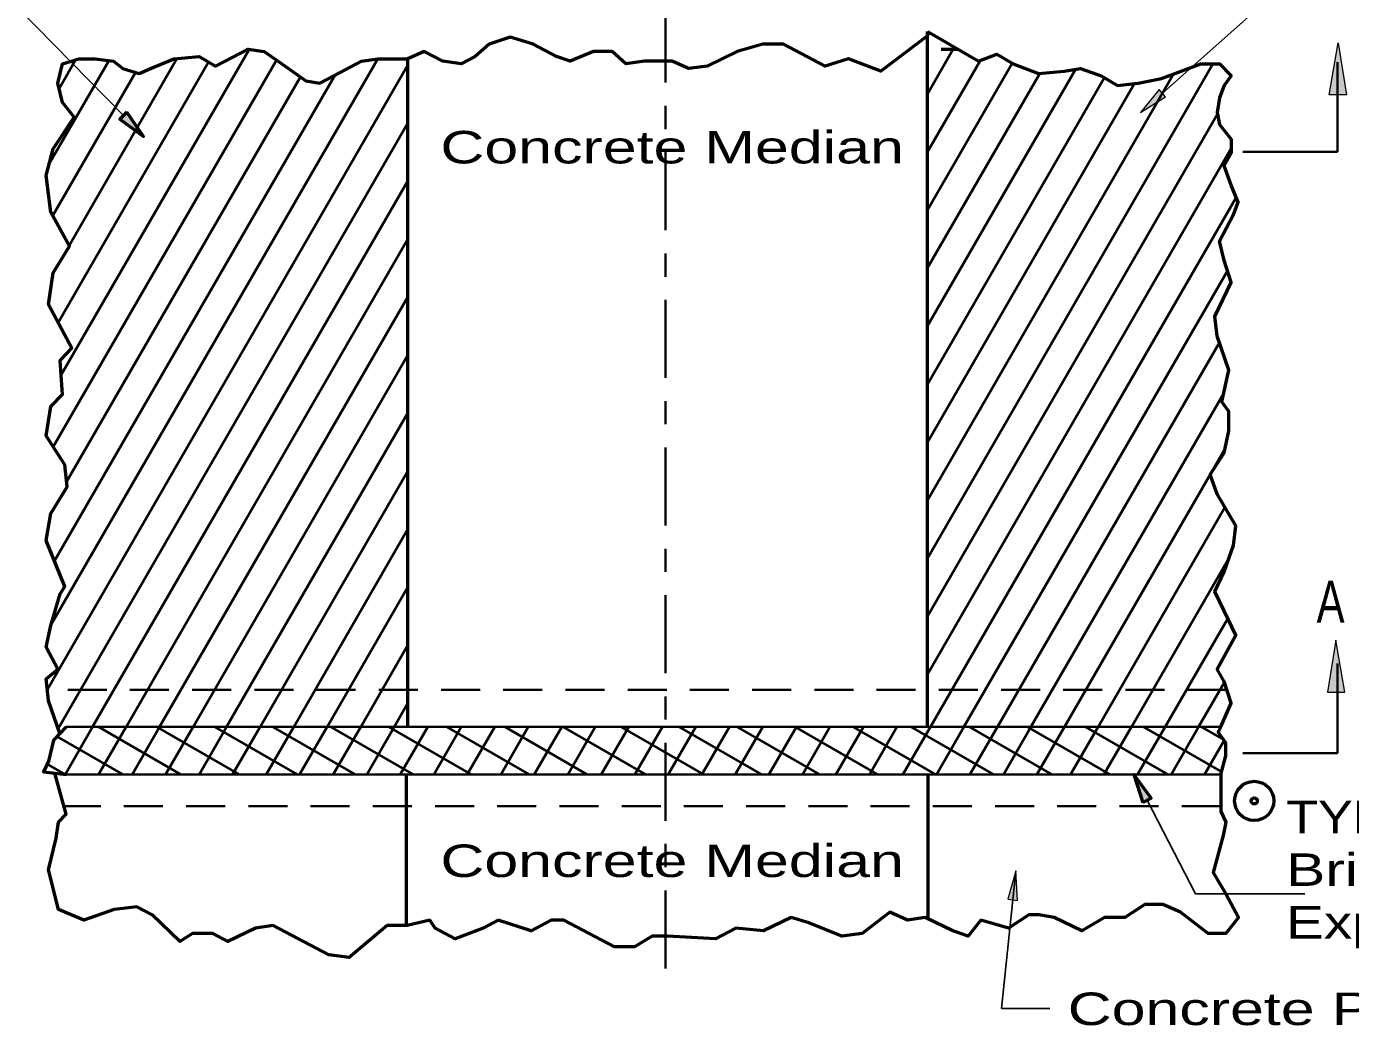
# Model space of a CAD drawing. Extents: x 14 to 49.3, y 28 to 50.
# Drawn here: x 18.68 to 24.38, y 41.95 to 46.26 of the extents above; entities that cross this region are included whole.
import ezdxf

# ---------------------------------------------------------------- set-up
doc = ezdxf.new("R2010")
doc.units = 0
doc.header["$LTSCALE"] = 0.056
doc.linetypes.add('LONG_DASH_SHORT_DASH', pattern=[9.9, 6, -1.2, 1.5, -1.2])
doc.linetypes.add('MEDIUM_DASHED', pattern=[4.5, 3, -1.5])
for name, color, linetype, lineweight in [('1', 7, 'Continuous', 35), ('2', 7, 'MEDIUM_DASHED', 35), ('3', 7, 'Continuous', 13), ('5', 7, 'Continuous', 35), ('7', 7, 'LONG_DASH_SHORT_DASH', 35)]:
    doc.layers.add(name, color=color, linetype=linetype, lineweight=lineweight)

msp = doc.modelspace()

# ---------------------------------------------------------------- hatches: boundary and pattern name
at = {"layer": '3'}
for points in [[(24.36125, 45.96333), (24.28642, 45.964), (24.32525, 46.188), (24.32525, 46.188)], [(23.58192, 45.95575), (23.55425, 45.98692), (23.47467, 45.88825), (23.47467, 45.88825)], [(19.10817, 45.889), (19.07833, 45.85975), (19.18067, 45.78508), (19.18067, 45.78508)], [(24.27917, 43.39033), (24.354, 43.391), (24.31517, 43.615), (24.31517, 43.615)], [(23.48367, 42.91517), (23.52067, 42.93433), (23.44467, 43.03575), (23.44467, 43.03575)], [(22.903, 42.49817), (22.94433, 42.49358), (22.93742, 42.62017), (22.93742, 42.62017)]]:
    msp.add_hatch(color=256, dxfattribs=at).paths.add_polyline_path(points)

# ---------------------------------------------------------------- linework, layer by layer
at = {"layer": '1', "lineweight": 53}
for p, q in [((22.556, 43.24125), (22.556, 46.23625)), ((22.61592, 46.16067), (22.68575, 46.16067)), ((20.31917, 43.24125), (20.31917, 46.11875)), ((20.31267, 42.385), (20.31267, 43.03575)), ((22.5595, 42.41308), (22.5595, 43.03575))]:
    msp.add_line(p, q, dxfattribs=at)
at = {"layer": '1', "lineweight": 40}
for p, q in [((22.556, 46.21808), (22.56383, 46.23167)), ((18.82558, 44.75692), (19.63558, 46.15983)), ((22.556, 45.96808), (22.67183, 46.16875)), ((18.76608, 43.40375), (20.31917, 46.09383)), ((18.7755, 45.67008), (19.03008, 46.111)), ((18.78275, 43.68267), (20.18917, 46.11875)), ((18.7915, 44.44775), (19.753, 46.11317)), ((18.81217, 44.98367), (19.45992, 46.10558)), ((18.81667, 45.9915), (18.88783, 46.11475)), ((18.85942, 45.3155), (19.32392, 46.12)), ((22.556, 45.71808), (22.78292, 46.11108)), ((22.556, 45.46808), (22.92108, 46.10042)), ((22.556, 43.96808), (23.78558, 46.09775)), ((18.78933, 45.44408), (19.14525, 46.06058)), ((18.79667, 43.95675), (20.00383, 46.04758)), ((18.84892, 44.29725), (19.85583, 46.04125)), ((22.556, 44.96808), (23.19433, 46.07375)), ((22.556, 45.21808), (23.03992, 46.05633)), ((22.556, 44.21808), (23.61592, 46.054)), ((22.556, 44.71808), (23.31783, 46.03767)), ((22.556, 44.46808), (23.44733, 46.012)), ((22.556, 43.71808), (23.80533, 45.88208)), ((18.81242, 43.234), (20.31917, 45.84383)), ((22.556, 43.46808), (23.86408, 45.73383)), ((18.96092, 43.24125), (20.31917, 45.59383)), ((22.56933, 43.24125), (23.88575, 45.52133)), ((19.10525, 43.24125), (20.31917, 45.34383)), ((22.71367, 43.24125), (23.848, 45.20592)), ((19.24958, 43.24125), (20.31917, 45.09383)), ((22.858, 43.24125), (23.81375, 44.89658)), ((19.39392, 43.24125), (20.31917, 44.84383)), ((23.00233, 43.24125), (23.83233, 44.67875)), ((19.53825, 43.24125), (20.31917, 44.59383)), ((23.14667, 43.24125), (23.83758, 44.43783)), ((19.68258, 43.24125), (20.31917, 44.34383)), ((23.29108, 43.24125), (23.83725, 44.18733)), ((19.82692, 43.24125), (20.31917, 44.09383)), ((23.43542, 43.24125), (23.85467, 43.96742)), ((19.97125, 43.24125), (20.31917, 43.84383)), ((23.57975, 43.24125), (23.8495, 43.7085)), ((20.11558, 43.24125), (20.31917, 43.59383)), ((23.72408, 43.24125), (23.83517, 43.43367)), ((20.25992, 43.24125), (20.31917, 43.34383)), ((18.84258, 43.03625), (18.96092, 43.24125)), ((18.98558, 43.24125), (19.3415, 43.03575)), ((18.98658, 43.03575), (19.10525, 43.24125)), ((19.13092, 43.03575), (19.24958, 43.24125)), ((19.23558, 43.24125), (19.5915, 43.03575)), ((19.27525, 43.03575), (19.39392, 43.24125)), ((19.41958, 43.03575), (19.53825, 43.24125)), ((19.48558, 43.24125), (19.8415, 43.03575)), ((19.56392, 43.03575), (19.68258, 43.24125)), ((19.70833, 43.03575), (19.82692, 43.24125)), ((19.73558, 43.24125), (20.0915, 43.03575)), ((19.85267, 43.03575), (19.97125, 43.24125)), ((19.98558, 43.24125), (20.3415, 43.03575)), ((19.997, 43.03575), (20.11558, 43.24125)), ((20.14133, 43.03575), (20.25992, 43.24125)), ((20.23558, 43.24125), (20.5915, 43.03575)), ((20.28567, 43.03575), (20.40433, 43.24125)), ((20.43, 43.03575), (20.54867, 43.24125)), ((20.48558, 43.24125), (20.8415, 43.03575)), ((20.57433, 43.03575), (20.693, 43.24125)), ((20.71867, 43.03575), (20.83733, 43.24125)), ((20.73558, 43.24125), (21.0915, 43.03575)), ((20.863, 43.03575), (20.98167, 43.24125)), ((20.98558, 43.24125), (21.3415, 43.03575)), ((21.00733, 43.03575), (21.126, 43.24125)), ((21.15167, 43.03575), (21.27033, 43.24125)), ((21.23558, 43.24125), (21.5915, 43.03575)), ((21.296, 43.03575), (21.41467, 43.24125)), ((21.44033, 43.03575), (21.559, 43.24125)), ((21.48558, 43.24125), (21.8415, 43.03575)), ((21.58467, 43.03575), (21.70333, 43.24125)), ((21.729, 43.03575), (21.84767, 43.24125)), ((21.73558, 43.24125), (22.0915, 43.03575)), ((21.87333, 43.03575), (21.992, 43.24125)), ((21.98558, 43.24125), (22.3415, 43.03575)), ((22.01767, 43.03575), (22.13633, 43.24125)), ((22.162, 43.03575), (22.28067, 43.24125)), ((22.23558, 43.24125), (22.5915, 43.03575)), ((22.30633, 43.03575), (22.425, 43.24125)), ((22.45075, 43.03575), (22.56933, 43.24125)), ((22.48558, 43.24125), (22.8415, 43.03575)), ((22.59508, 43.03575), (22.71367, 43.24125)), ((22.73558, 43.24125), (23.0915, 43.03575)), ((22.73942, 43.03575), (22.858, 43.24125)), ((22.88375, 43.03575), (23.00233, 43.24125)), ((22.98558, 43.24125), (23.3415, 43.03575)), ((23.02808, 43.03575), (23.14667, 43.24125)), ((23.17242, 43.03575), (23.29108, 43.24125)), ((23.23558, 43.24125), (23.5915, 43.03575)), ((23.31675, 43.03575), (23.43542, 43.24125)), ((23.46108, 43.03575), (23.57975, 43.24125)), ((23.48558, 43.24125), (23.82267, 43.04658)), ((23.60542, 43.03575), (23.72408, 43.24125)), ((23.73558, 43.24125), (23.83258, 43.18525)), ((18.80742, 43.19975), (19.0915, 43.03575)), ((23.74975, 43.03575), (23.8345, 43.18258)), ((18.76475, 43.08008), (18.84017, 43.0365))]:
    msp.add_line(p, q, dxfattribs=at)
at = {"layer": '1'}
for p, q in [((22.556, 43.24125), (18.847, 43.24125)), ((23.81975, 43.24125), (22.556, 43.24125)), ((18.847, 43.03575), (23.81975, 43.03575))]:
    msp.add_line(p, q, dxfattribs=at)
at = {"layer": '1', "lineweight": 53}
for points in [[(22.556, 46.21808), (22.35625, 46.06633), (22.21642, 46.11875), (22.11658, 46.08733), (21.93683, 46.18158), (21.847, 46.18158), (21.73717, 46.15017), (21.60733, 46.08733), (21.52742, 46.07683), (21.4575, 46.10825), (21.33775, 46.10825), (21.25783, 46.09775), (21.19792, 46.15017), (21.118, 46.15017), (21.01817, 46.10825), (20.95825, 46.12925), (20.85842, 46.18158), (20.75858, 46.213), (20.66867, 46.18158), (20.60875, 46.12925), (20.54883, 46.09775), (20.469, 46.10825), (20.38908, 46.15017), (20.31917, 46.11875)], [(22.556, 46.23625), (22.77567, 46.10825), (22.8555, 46.13967), (22.92542, 46.09775), (23.03525, 46.05592), (23.14508, 46.06633), (23.215, 46.07683), (23.30492, 46.04542), (23.37475, 46.0035), (23.46467, 46.014), (23.5645, 46.03492), (23.73425, 46.09775), (23.81417, 46.09775), (23.86408, 46.04542), (23.83417, 46.0035), (23.81417, 45.95117), (23.80417, 45.88825), (23.81417, 45.83592), (23.86408, 45.77308), (23.86408, 45.7105)], [(18.81975, 43.21267), (18.77142, 43.35325), (18.76142, 43.4475), (18.81133, 43.48942), (18.76142, 43.58367), (18.78142, 43.678), (18.82133, 43.81417), (18.84133, 43.84558), (18.76142, 44.04458), (18.78142, 44.15983), (18.85125, 44.27508), (18.84133, 44.36933), (18.76142, 44.49508), (18.78142, 44.62075), (18.83133, 44.67317), (18.82133, 44.81983), (18.87125, 44.87217), (18.77142, 45.06075), (18.79133, 45.19692), (18.86125, 45.31217), (18.78142, 45.45875), (18.76142, 45.61592), (18.79133, 45.73117), (18.88125, 45.86733), (18.83133, 45.93017), (18.81133, 46.014), (18.83133, 46.09775), (18.90125, 46.11875), (18.97108, 46.11875), (19.051, 46.10825), (19.09092, 46.07683), (19.16083, 46.05592), (19.21075, 46.07683), (19.31058, 46.11875), (19.4205, 46.12925), (19.49033, 46.08733), (19.63017, 46.16067), (19.70008, 46.15017), (19.78992, 46.08733), (19.87983, 46.02442)], [(19.87983, 46.02442), (19.93975, 46.014), (19.99967, 46.04542), (20.1195, 46.10825), (20.18933, 46.11875), (20.31917, 46.11875)], [(23.81975, 43.24125), (23.86408, 43.34258), (23.83417, 43.43683), (23.80417, 43.48925), (23.88408, 43.63592), (23.83417, 43.74075), (23.79425, 43.8245), (23.83417, 43.90833), (23.87408, 44.02358), (23.88408, 44.10742), (23.80417, 44.24367), (23.77425, 44.3275), (23.83417, 44.42175), (23.85417, 44.51608), (23.85417, 44.59983), (23.82417, 44.64175), (23.85417, 44.778), (23.80417, 44.92467), (23.79425, 45.0085), (23.86408, 45.15517), (23.83417, 45.2495), (23.81417, 45.33333), (23.87408, 45.44858), (23.89408, 45.50092), (23.86408, 45.57425), (23.83417, 45.65808), (23.86408, 45.7105)], [(18.847, 43.24125), (18.79258, 43.18417), (18.77075, 43.09283), (18.749, 43.04717), (18.847, 43.03575)], [(23.81975, 43.03575), (23.8415, 43.11567), (23.8415, 43.17275), (23.80883, 43.21842), (23.81975, 43.24125)], [(20.70767, 42.40783), (20.64242, 42.37358), (20.52267, 42.32792), (20.43567, 42.37358), (20.41383, 42.40783), (20.31592, 42.385), (20.22892, 42.385), (20.06567, 42.248), (19.97858, 42.25942), (19.73925, 42.385), (19.66308, 42.37358), (19.54333, 42.3165), (19.47808, 42.35075), (19.391, 42.35075), (19.33658, 42.3165), (19.21692, 42.43067), (19.15167, 42.46492), (19.05367, 42.4535), (18.92317, 42.40783), (18.81433, 42.4535), (18.77075, 42.62475), (18.80342, 42.76175), (18.81433, 42.83025), (18.847, 42.8645), (18.798, 43.04142)], [(23.81975, 43.03575), (23.81975, 42.87592), (23.8415, 42.83025), (23.83058, 42.77317), (23.78708, 42.61333), (23.8415, 42.522), (23.89592, 42.41925), (23.8415, 42.35075), (23.76533, 42.35075), (23.64567, 42.44208), (23.5695, 42.47633), (23.49333, 42.47633), (23.40625, 42.41925), (23.31917, 42.41925), (23.22125, 42.36217), (23.10158, 42.41925), (23.03625, 42.43067), (22.99275, 42.43067), (22.90567, 42.37358), (22.786, 42.40783), (22.73158, 42.33933), (22.66633, 42.36217), (22.54658, 42.41925), (22.47042, 42.40783), (22.39425, 42.44208), (22.27458, 42.35075), (22.1875, 42.33933), (22.04608, 42.39642), (21.96992, 42.41925), (21.85025, 42.36217), (21.7305, 42.37358), (21.6435, 42.32792), (21.43675, 42.33933), (21.37142, 42.33933), (21.29525, 42.29367), (21.20825, 42.29367), (20.99058, 42.40783), (20.93617, 42.40783), (20.84917, 42.36217), (20.70767, 42.40783)]]:
    msp.add_lwpolyline(points, dxfattribs=at)
at = {"layer": '2'}
for p, q in [((23.8455, 43.40108), (18.76633, 43.40108)), ((23.81975, 42.89875), (18.8375, 42.89875))]:
    msp.add_line(p, q, dxfattribs=at)
at = {"layer": '3', "lineweight": 25}
for p, q in [((22.93742, 42.62017), (22.87558, 42.027)), ((22.87558, 42.027), (23.08358, 42.027))]:
    msp.add_line(p, q, dxfattribs=at)
for points in [[(19.09325, 45.87442), (18.34083, 46.643), (18.54708, 46.643)], [(23.56808, 45.97133), (24.32342, 46.6425), (24.07375, 46.6425)], [(23.50217, 42.92475), (23.71092, 42.52175), (24.18125, 42.52175)]]:
    msp.add_lwpolyline(points, dxfattribs=at)
at = {"layer": '3'}
for points in [[(24.36125, 45.96333), (24.28642, 45.964), (24.32525, 46.188), (24.32525, 46.188)], [(23.58192, 45.95575), (23.55425, 45.98692), (23.47467, 45.88825), (23.47467, 45.88825)], [(24.27917, 43.39033), (24.354, 43.391), (24.31517, 43.615), (24.31517, 43.615)], [(22.903, 42.49817), (22.94433, 42.49358), (22.93742, 42.62017), (22.93742, 42.62017)]]:
    msp.add_lwpolyline(points, close=True, dxfattribs=at)
at = {"layer": '3', "lineweight": 53}
for points in [[(19.10817, 45.889), (19.07833, 45.85975), (19.18067, 45.78508), (19.18067, 45.78508)], [(23.48367, 42.91517), (23.52067, 42.93433), (23.44467, 43.03575), (23.44467, 43.03575)]]:
    msp.add_lwpolyline(points, close=True, dxfattribs=at)
for radius in [0.08431, 0.01331]:
    msp.add_circle((23.96383, 42.92217), radius, dxfattribs=at)
at = {"layer": '5'}
for p, q in [((24.323, 46.10508), (24.323, 45.71892)), ((23.91442, 45.71892), (24.323, 45.71892)), ((24.323, 43.51425), (24.323, 43.12808)), ((23.91442, 43.12808), (24.323, 43.12808))]:
    msp.add_line(p, q, dxfattribs=at)
at = {"layer": '7'}
msp.add_line((21.42758, 42.2005), (21.42758, 46.49608), dxfattribs=at)

# ---------------------------------------------------------------- texts
at = {"layer": '3'}
for s, width, p in [('Concrete Median', 1.4, (20.45892, 45.66833)), ('TYPE J JOINT:', 1.2, (24.10142, 42.7825)), ('Concrete Median', 1.4, (20.45892, 42.59408)), ('Bridge Approach', 1.35, (24.10142, 42.55583)), ('Expansion Joint', 1.3, (24.10142, 42.32917)), ('Concrete Pavement', 1.4, (23.16058, 41.95625))]:
    msp.add_text(s, height=0.14, dxfattribs=dict(at, width=width)).set_placement(p)
at = {"layer": '5', "width": 0.75}
msp.add_text('A', height=0.18, dxfattribs=at).set_placement((24.2325, 43.69033))

doc.saveas('drawing.dxf')
